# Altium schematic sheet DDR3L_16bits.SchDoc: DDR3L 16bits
size A3; Date: Not used; ApprovedBy: Not used; CheckedBy: Not used; Author: Not used; CompanyName: STMicroelectronics; DrawnBy: Not used; Engineer: Not used; Organization: Not used; Address1: Not used; Address2: Not used; Address3: Not used; Address4: Not used; DocumentNumber: 6; Revision: Not used; SheetNumber: 6; SheetTotal: 17
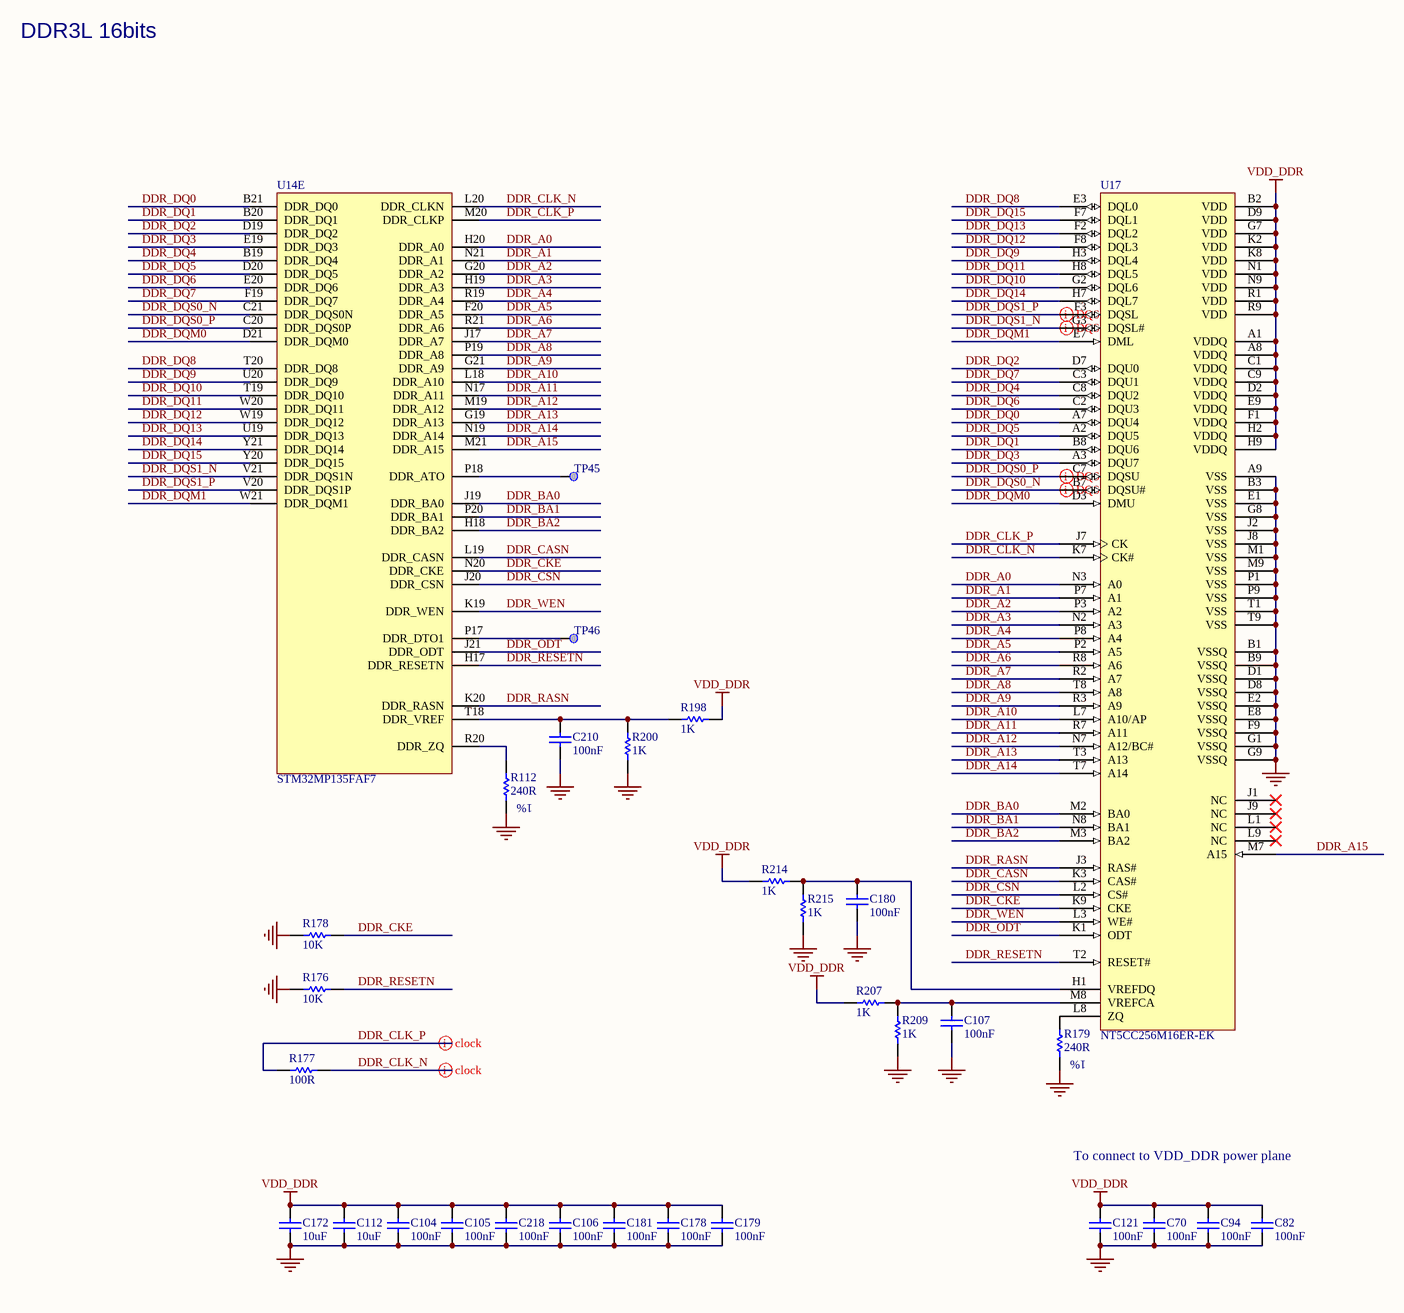
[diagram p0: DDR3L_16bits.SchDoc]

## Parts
C70  value 100nF  [C0402]  (hidden comment: Capacitor)
C82  value 100nF  [C0402]  (hidden comment: Capacitor)
C94  value 100nF  [C0402]  (hidden comment: Capacitor)
C104  value 100nF  [C0402]  (hidden comment: Capacitor)
C105  value 100nF  [C0402]  (hidden comment: Capacitor)
C106  value 100nF  [C0402]  (hidden comment: Capacitor)
C107  value 100nF  [C0402]  (hidden comment: Capacitor)
C112  value 10uF  [C0603]  (hidden comment: Capacitor)
C121  value 100nF  [C0402]  (hidden comment: Capacitor)
C172  value 10uF  [C0603]  (hidden comment: Capacitor)
C178  value 100nF  [C0402]  (hidden comment: Capacitor)
C179  value 100nF  [C0402]  (hidden comment: Capacitor)
C180  value 100nF  [C0402]  (hidden comment: Capacitor)
C181  value 100nF  [C0402]  (hidden comment: Capacitor)
C210  value 100nF  [C0402]  (hidden comment: Capacitor)
C218  value 100nF  [C0402]  (hidden comment: Capacitor)
R112  value 240R  [R0402]  (hidden comment: Resistor)
R176  value 10K  [R0402]  (hidden comment: Resistor)
R177  value 100R  [R0402]  (hidden comment: Resistor)
R178  value 10K  [R0402]  (hidden comment: Resistor)
R179  value 240R  [R0402]  (hidden comment: Resistor)
R198  value 1K  [R0402]  (hidden comment: Resistor)
R200  value 1K  [R0402]  (hidden comment: Resistor)
R207  value 1K  [R0402]  (hidden comment: Resistor)
R209  value 1K  [R0402]  (hidden comment: Resistor)
R214  value 1K  [R0402]  (hidden comment: Resistor)
R215  value 1K  [R0402]  (hidden comment: Resistor)
TP45  Test Point  [TP_SMD_1MM]  (value not drawn)  (no BOM)
TP46  Test Point  [TP_SMD_1MM]  (value not drawn)  (no BOM)
U14  STM32MP135FAF7  [ICC_TFBGA320_11X11_STM32MP135FA7_P050_H1P20]  (part E of 5)
U17  NT5CC256M16ER-EK  [ICC_VFBGA96_9x13_P080]

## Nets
GND: C70.1 C82.1 C94.1 C104.1 C105.1 C106.1 C107.2 C112.1 C121.1 C172.1 C178.1 C179.1 C180.2 C181.1 C210.2 C218.1 R112.1 R176.1 R178.1 R179.1 R200.1 R209.1 R215.1 U17.A9(VSS) U17.B1(VSSQ) U17.B3(VSS) U17.B9(VSSQ) U17.D1(VSSQ) U17.D8(VSSQ) U17.E1(VSS) U17.E2(VSSQ) U17.E8(VSSQ) U17.F9(VSSQ) U17.G1(VSSQ) U17.G8(VSS) U17.G9(VSSQ) U17.J2(VSS) U17.J8(VSS) U17.M1(VSS) U17.M9(VSS) U17.P1(VSS) U17.P9(VSS) U17.T1(VSS) U17.T9(VSS)
VDD_DDR: C70.2 C82.2 C94.2 C104.2 C105.2 C106.2 C112.2 C121.2 C172.2 C178.2 C179.2 C181.2 C218.2 R198.2 R207.1 R214.1 U17.A1(VDDQ) U17.A8(VDDQ) U17.B2(VDD) U17.C1(VDDQ) U17.C9(VDDQ) U17.D2(VDDQ) U17.D9(VDD) U17.E9(VDDQ) U17.F1(VDDQ) U17.G7(VDD) U17.H2(VDDQ) U17.H9(VDDQ) U17.K2(VDD) U17.K8(VDD) U17.N1(VDD) U17.N9(VDD) U17.R1(VDD) U17.R9(VDD)
DDR_A0: U14.H20(DDR_A0) U17.N3(A0)
DDR_A1: U14.N21(DDR_A1) U17.P7(A1)
DDR_A2: U14.G20(DDR_A2) U17.P3(A2)
DDR_A3: U14.H19(DDR_A3) U17.N2(A3)
DDR_A4: U14.R19(DDR_A4) U17.P8(A4)
DDR_A5: U14.F20(DDR_A5) U17.P2(A5)
DDR_A6: U14.R21(DDR_A6) U17.R8(A6)
DDR_A7: U14.J17(DDR_A7) U17.R2(A7)
DDR_A8: U14.P19(DDR_A8) U17.T8(A8)
DDR_A9: U14.G21(DDR_A9) U17.R3(A9)
DDR_A10: U14.L18(DDR_A10) U17.L7(A10/AP)
DDR_A11: U14.N17(DDR_A11) U17.R7(A11)
DDR_A12: U14.M19(DDR_A12) U17.N7(A12/BC#)
DDR_A13: U14.G19(DDR_A13) U17.T3(A13)
DDR_A14: U14.N19(DDR_A14) U17.T7(A14)
DDR_A15: U14.M21(DDR_A15) U17.M7(A15)
DDR_BA0: U14.J19(DDR_BA0) U17.M2(BA0)
DDR_BA1: U14.P20(DDR_BA1) U17.N8(BA1)
DDR_BA2: U14.H18(DDR_BA2) U17.M3(BA2)
DDR_CASN: U14.L19(DDR_CASN) U17.K3(CAS#)
DDR_CKE: R178.2 U14.N20(DDR_CKE) U17.K9(CKE)
DDR_CLK_N: R177.2 U14.L20(DDR_CLKN) U17.K7(CK#)
DDR_CLK_P: R177.1 U14.M20(DDR_CLKP) U17.J7(CK)
DDR_CSN: U14.J20(DDR_CSN) U17.L2(CS#)
DDR_DQ0: U14.B21(DDR_DQ0) U17.A7(DQU4)
DDR_DQ1: U14.B20(DDR_DQ1) U17.B8(DQU6)
DDR_DQ2: U14.D19(DDR_DQ2) U17.D7(DQU0)
DDR_DQ3: U14.E19(DDR_DQ3) U17.A3(DQU7)
DDR_DQ4: U14.B19(DDR_DQ4) U17.C8(DQU2)
DDR_DQ5: U14.D20(DDR_DQ5) U17.A2(DQU5)
DDR_DQ6: U14.E20(DDR_DQ6) U17.C2(DQU3)
DDR_DQ7: U14.F19(DDR_DQ7) U17.C3(DQU1)
DDR_DQ8: U14.T20(DDR_DQ8) U17.E3(DQL0)
DDR_DQ9: U14.U20(DDR_DQ9) U17.H3(DQL4)
DDR_DQ10: U14.T19(DDR_DQ10) U17.G2(DQL6)
DDR_DQ11: U14.W20(DDR_DQ11) U17.H8(DQL5)
DDR_DQ12: U14.W19(DDR_DQ12) U17.F8(DQL3)
DDR_DQ13: U14.U19(DDR_DQ13) U17.F2(DQL2)
DDR_DQ14: U14.Y21(DDR_DQ14) U17.H7(DQL7)
DDR_DQ15: U14.Y20(DDR_DQ15) U17.F7(DQL1)
DDR_DQM0: U14.D21(DDR_DQM0) U17.D3(DMU)
DDR_DQM1: U14.W21(DDR_DQM1) U17.E7(DML)
DDR_DQS0_N: U14.C21(DDR_DQS0N) U17.B7(DQSU#)
DDR_DQS0_P: U14.C20(DDR_DQS0P) U17.C7(DQSU)
DDR_DQS1_N: U14.V21(DDR_DQS1N) U17.G3(DQSL#)
DDR_DQS1_P: U14.V20(DDR_DQS1P) U17.F3(DQSL)
DDR_ODT: U14.J21(DDR_ODT) U17.K1(ODT)
DDR_RASN: U14.K20(DDR_RASN) U17.J3(RAS#)
DDR_RESETN: R176.2 U14.H17(DDR_RESETN) U17.T2(RESET#)
DDR_WEN: U14.K19(DDR_WEN) U17.L3(WE#)
NetC107_1: C107.1 R207.2 R209.2 U17.M8(VREFCA)
NetC180_1: C180.1 R214.2 R215.2 U17.H1(VREFDQ)
NetC210_1: C210.1 R198.1 R200.2 U14.T18(DDR_VREF)
NetR112_2: R112.2 U14.R20(DDR_ZQ)
NetR179_2: R179.2 U17.L8(ZQ)
NetTP45_1: TP45.1 U14.P18(DDR_ATO)
NetTP46_1: TP46.1 U14.P17(DDR_DTO1)

Not connected (* = marked no-connect by the designer): U17 J1(NC)* J9(NC)* L1(NC)* L9(NC)*

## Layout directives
differential pair: DDR_CLK_N, DDR_CLK_P, DDR_DQS0_N, DDR_DQS0_P, DDR_DQS1_N, DDR_DQS1_P

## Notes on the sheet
- DDR3L 16bits
- (near R112) 1%
- (near R179) 1%
- To connect to VDD_DDR power plane

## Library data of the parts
C70 C82 C94 C104-C106 C121 C178 C179 C181 C210 C218 = MCD-00006: Capacitor, MLCC, 100nF, 16V, X7R, +/-10%, 0402, T=0.5mm; Manufacturer: YAGEO; Manufacturer_Part_Number: CC0402KRX7R7BB104; Part_Preference: Recommended; Partial_Alternate_Internal_Part_Number: MCD-03299; Order_Code_RS: 9402047; Component_Country_Of_Origin: China; ShowFields: YES; ID: 2474
C107 C180 = MCD-00006: Capacitor, MLCC, 100nF, 16V, X7R, +/-10%, 0402, T=0.5mm; Manufacturer_Part_Number: CC0402KRX7R7BB104; Manufacturer: YAGEO; Part_Preference: Recommended; Partial_Alternate_Internal_Part_Number: MCD-03299; Order_Code_RS: 9402047; Component_Country_Of_Origin: China; ShowFields: YES; ID: 2474
C112 C172 = MCD-00099: Capacitor, MLCC, 10uF, 10V, X5R, +/-10%, 0603, T=0.8mm; Manufacturer_Part_Number: GRM188R61A106KE69; Manufacturer: MURATA; Part_Preference: Recommended; Partial_Alternate_Internal_Part_Number: MCD-03152; Order_Code_RS: 2494233; Component_Country_Of_Origin: Japan°°; ShowFields: YES; ID: 2770
R112 = MCD-00120: Resistor, 240R, 0402, +/-1%, 1/16W; Manufacturer: YAGEO; Manufacturer_Part_Number: RC0402FR-07240RL; Part_Preference: Recommended; Component_Country_Of_Origin: China; ShowFields: YES; ID: 2745
R176 R178 = MCD-00053: Resistor, 10K, 0402, +/-1%, 1/16W; Manufacturer_Part_Number: RC0402FR-0710KL; Manufacturer: YAGEO; BMS_Part_Number: 9131590; Part_Preference: Recommended; Order_Code_RS: 9239359; Component_Country_Of_Origin: China; ShowFields: YES; ID: 2539
R177 = MCD-00067: Resistor, 100R, 0402, +/- 1%, 1/16W; Manufacturer_Part_Number: RC0402FR-07100RL; Manufacturer: YAGEO; Part_Preference: Recommended; Order_Code_RS: 9239111; Component_Country_Of_Origin: China; ShowFields: YES; ID: 2527
R179 = MCD-00120: Resistor, 240R, 0402, +/-1%, 1/16W; Manufacturer_Part_Number: RC0402FR-07240RL; Manufacturer: YAGEO; Part_Preference: Recommended; Component_Country_Of_Origin: China; ShowFields: YES; ID: 2745
R198 R200 R207 R209 R214 R215 = MCD-00061: Resistor, 1K, 0402, +/-1%,1/16W; Part_Preference: Recommended; Manufacturer: YAGEO; Manufacturer_Part_Number: RC0402FR-071KL; Order_Code_RS: 9239235; Component_Country_Of_Origin: China; ShowFields: YES; ID: 2532
TP45 TP46 = MCD-00074: Test Point 1mm; Part_Type: Misc; Part_Preference: Recommended; ShowFields: YES; ID: 2518; Component_Country_Of_Origin: Unknown
U14 = MCD-02251: Cortex-A7 @ 900MHz, 128KB-ROM, 128KB-SRAM, 2x Ethernet, 2x ADC, 2x CAN FD, TSC, Camera, Display, Secure Boot, Cryptography, DRAM enc/dec, PKA; Part_Preference: Recommended; Part_Type: IC; Manufacturer: STMICROELECTRONICS; Manufacturer_HQ_COO: EU; Component_Country_Of_Origin: Unknown; ShowFields: YES; ID: 4351
U17 = MCD-01811: Memory,DDR3L,4Gb,256Mbx16,933Mhz,1V35,TFBGA; Part_Preference: Recommended; Part_Type: IC; Manufacturer: NANYA; BMS_Part_Number: 9171435; Component_Country_Of_Origin: Taiwan; ShowFields: YES; ID: 3911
